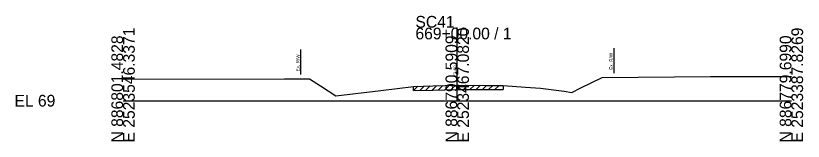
# Model space of a CAD drawing. Extents: x -26 to 183, y -10 to 24021.
# Drawn here: x -25.7 to 162.8, y 1990.3 to 2020.3 of the extents above; entities that cross this region are included whole.
import ezdxf

# ---------------------------------------------------------------- set-up
doc = ezdxf.new("R2010")
doc.units = 0
for name, color, linetype in [('RD_GPK_XS_Cell', 7, 'Continuous'), ('RD_XS_ExGround', 7, 'Continuous'), ('RD_XS_ExPaveRet', 7, 'Continuous'), ('RD_XS_ExRW', 7, 'Continuous'), ('RD_XS_TX_Elev_EX', 7, 'Continuous')]:
    doc.layers.add(name, color=color, linetype=linetype)

msp = doc.modelspace()

# ---------------------------------------------------------------- linework, layer by layer
at = {"layer": 'RD_GPK_XS_Cell'}
for p, q in [((80, 2000), (80, 2017.47)), ((0, 2000), (80, 2000)), ((80, 2000), (160, 2000))]:
    msp.add_line(p, q, dxfattribs=at)
at = {"layer": 'RD_XS_ExGround'}
for p, q in [((0, 2005.15), (38.64, 2005.24)), ((38.64, 2005.24), (44.66, 2005.24)), ((44.66, 2005.24), (47.26, 2003.56)), ((109.63, 2003.08), (114.68, 2005.58)), ((114.68, 2005.58), (140.67, 2005.77)), ((140.67, 2005.77), (160, 2005.82)), ((47.26, 2003.56), (50.93, 2001.16)), ((50.93, 2001.16), (61.71, 2002.47)), ((61.71, 2002.47), (69.52, 2003.42)), ((69.52, 2003.42), (74.13, 2003.53)), ((74.13, 2003.53), (80, 2003.69)), ((80, 2003.69), (80.37, 2003.7)), ((80.37, 2003.7), (86.57, 2003.66)), ((86.57, 2003.66), (90.96, 2003.64)), ((90.96, 2003.64), (96.31, 2003.27)), ((96.31, 2003.27), (99.9, 2002.99)), ((99.9, 2002.99), (105.6, 2002.26)), ((105.6, 2002.26), (107.44, 2001.93)), ((107.44, 2001.93), (109.63, 2003.08))]:
    msp.add_line(p, q, dxfattribs=at)
at = {"layer": 'RD_XS_ExPaveRet'}
for p, q in [((69.52, 2002.42), (70.55, 2003.44)), ((69.52, 2002.42), (69.52, 2003.42)), ((69.52, 2002.42), (74.13, 2002.53)), ((71.02, 2002.45), (72.05, 2003.48)), ((72.52, 2002.49), (73.55, 2003.52)), ((74.02, 2002.53), (75.05, 2003.56)), ((74.13, 2002.53), (80, 2002.69)), ((75.52, 2002.57), (76.55, 2003.6)), ((77.02, 2002.61), (78.05, 2003.64)), ((78.52, 2002.65), (79.55, 2003.68)), ((80, 2002.69), (80.37, 2002.7)), ((80.02, 2002.69), (81.03, 2003.7)), ((80.37, 2002.7), (86.57, 2002.66)), ((81.52, 2002.69), (82.52, 2003.69)), ((83.02, 2002.68), (84.02, 2003.67)), ((84.52, 2002.67), (85.52, 2003.66)), ((86.02, 2002.66), (87.02, 2003.65)), ((86.57, 2002.66), (90.96, 2002.64)), ((87.52, 2002.65), (88.52, 2003.65)), ((89.02, 2002.65), (90.02, 2003.64)), ((90.96, 2003.64), (90.96, 2002.64))]:
    msp.add_line(p, q, dxfattribs=at)
at = {"layer": 'RD_XS_ExRW'}
for p, q in [((42.5, 2012.24), (42.5, 2006.24)), ((117.5, 2012.6), (117.5, 2006.6))]:
    msp.add_line(p, q, dxfattribs=at)

# ---------------------------------------------------------------- texts
at = {"layer": 'RD_GPK_XS_Cell'}
for s, p in [('SC41', (70, 2017.47)), ('669+00.00 / 1', (70, 2014.67)), ('EL 69', (-26, 1998.6))]:
    msp.add_text(s, height=2.8, dxfattribs=at).set_placement(p)
for s, p in [('E 2523546.3371', (2.8, 1990)), ('E 2523467.0820', (82.8, 1990)), ('E 2523387.8269', (162.8, 1990)), ('N 886801.4828', (0, 1990)), ('N 886790.5909', (80, 1990)), ('N 886779.6990', (160, 1990))]:
    msp.add_text(s, height=2.8, rotation=90, dxfattribs=at).set_placement(p)
at = {"layer": 'RD_XS_ExRW'}
for p in [(42.25, 2007.02), (117.25, 2007.39)]:
    msp.add_text('Ex. R/W ', height=0.8, rotation=90, dxfattribs=at).set_placement(p)
at = {"layer": 'RD_XS_TX_Elev_EX'}
msp.add_text('72.69', height=0.8, rotation=90, dxfattribs=at).set_placement((79.9, 2005.69))

doc.saveas('drawing.dxf')
